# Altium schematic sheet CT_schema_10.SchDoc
size 387 x 278 mm
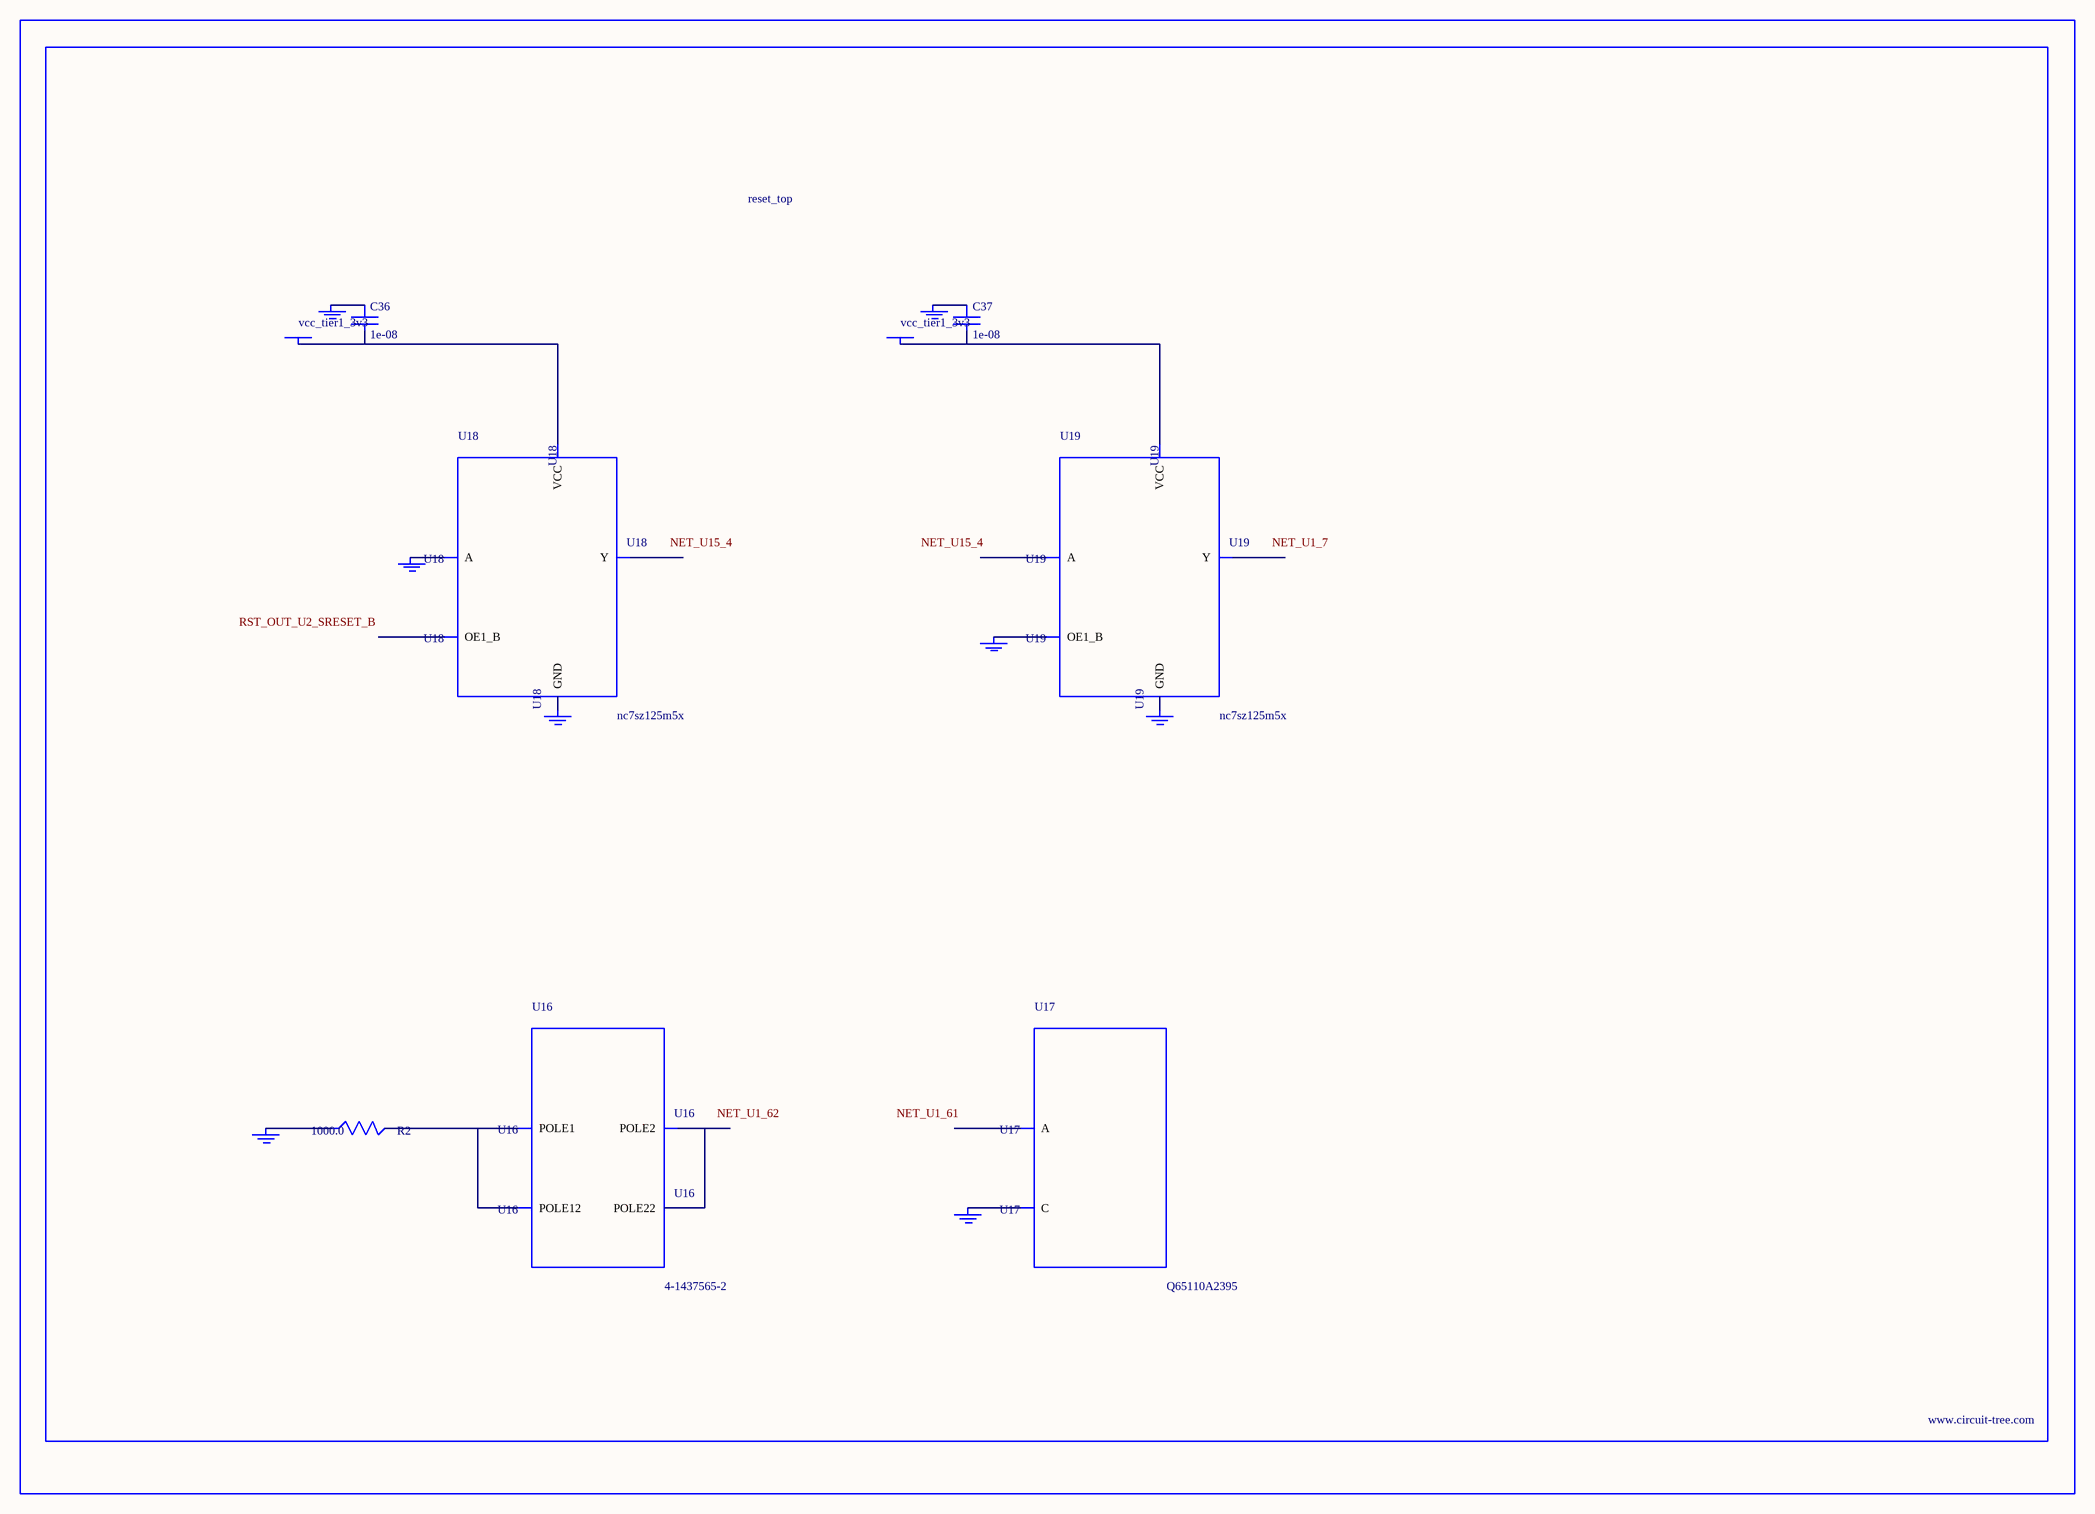
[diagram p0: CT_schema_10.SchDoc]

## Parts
BORDER9  (no value)
C36  1e-08  [C0402]
C37  1e-08  [C0402]
GND_INSTANCE_9_0  (no value)
GND_INSTANCE_9_1  (no value)
GND_INSTANCE_9_2  (no value)
GND_INSTANCE_9_3  (no value)
GND_INSTANCE_9_4  (no value)
GND_INSTANCE_9_5  (no value)
GND_INSTANCE_9_6  (no value)
GND_INSTANCE_9_7  (no value)
POWER_INSTANCE_9_0  vcc_tier1_3v3
POWER_INSTANCE_9_1  vcc_tier1_3v3
R2  1000.0  [R0603]
U16  4-1437565-2  [SW_4-1437565-2]
U17  Q65110A2395  [LGM67K-G1J2-24-Z]
U18  nc7sz125m5x  [NC7SZ125M5X]
U19  nc7sz125m5x  [NC7SZ125M5X]

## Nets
NetC36_1: C36.1 GND_INSTANCE_9_2.0(GND)
NetC36_2: C36.2 POWER_INSTANCE_9_0.0(PWR) U18.5(VCC)
NetC37_1: C37.1 GND_INSTANCE_9_5.0(GND)
NetC37_2: C37.2 POWER_INSTANCE_9_1.0(PWR) U19.5(VCC)
NetGND_INSTANCE_9_0_0: GND_INSTANCE_9_0.0(GND) R2.1
NetGND_INSTANCE_9_1_0: GND_INSTANCE_9_1.0(GND) U17.C
NetGND_INSTANCE_9_3_0: GND_INSTANCE_9_3.0(GND) U18.2(A)
NetGND_INSTANCE_9_4_0: GND_INSTANCE_9_4.0(GND) U18.3(GND)
NetGND_INSTANCE_9_6_0: GND_INSTANCE_9_6.0(GND) U19.1(OE1_B)
NetGND_INSTANCE_9_7_0: GND_INSTANCE_9_7.0(GND) U19.3(GND)
NetR2_2: R2.2 U16.1(POLE1) U16.2(POLE12)
NetU16_3: U16.3(POLE2) U16.4(POLE22)

Not connected (* = marked no-connect by the designer): U17 A; U18 1(OE1_B) 4(Y); U19 2(A) 4(Y)

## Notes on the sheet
- Labels drawn without touching a wire or pin: NET_U1_7, NET_U1_61, NET_U1_62, NET_U15_4, RST_OUT_U2_SRESET_B

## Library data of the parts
BORDER9 = BORDER_PAGE9
C36 C37 = C0402C103K3RAC
GND_INSTANCE_9_0-GND_INSTANCE_9_7 = GND
POWER_INSTANCE_9_0 POWER_INSTANCE_9_1 = PWR
R2 = RC0603JR-071KL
